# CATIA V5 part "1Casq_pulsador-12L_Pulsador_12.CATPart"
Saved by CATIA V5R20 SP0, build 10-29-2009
Part number: 1Casq_pulsador-12L_Pulsador_12
Revision: ANY
Definition: UNKNOWN
Nomenclature: 1Casq_pulsador-12L_Pulsador_12
Source: Unknown
Bounding box of the stored display mesh (mm): x -9.8 to 9.8, y 0 to 14.3, z -9.8 to 9.8
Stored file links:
  C:\Users\Utente\Desktop\IO LAVORO\3D X SITO CF\CUMSA\3D files BA\BA 122024\1Casq_pulsador-12L_Pulsador_12.CATPart
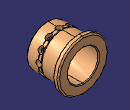
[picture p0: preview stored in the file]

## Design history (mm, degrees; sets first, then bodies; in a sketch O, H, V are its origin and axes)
Body1 "MatrizC1" (main body)
  Solid1: solid without history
